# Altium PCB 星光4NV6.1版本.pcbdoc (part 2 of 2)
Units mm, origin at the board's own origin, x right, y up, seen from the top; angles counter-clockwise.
Board outline 96.4 x 47 mm, 2 copper layers (Top Layer, Bottom Layer), stack 1.58 mm thick; 27 components, 21 nets, 135 pads, 175 vias.
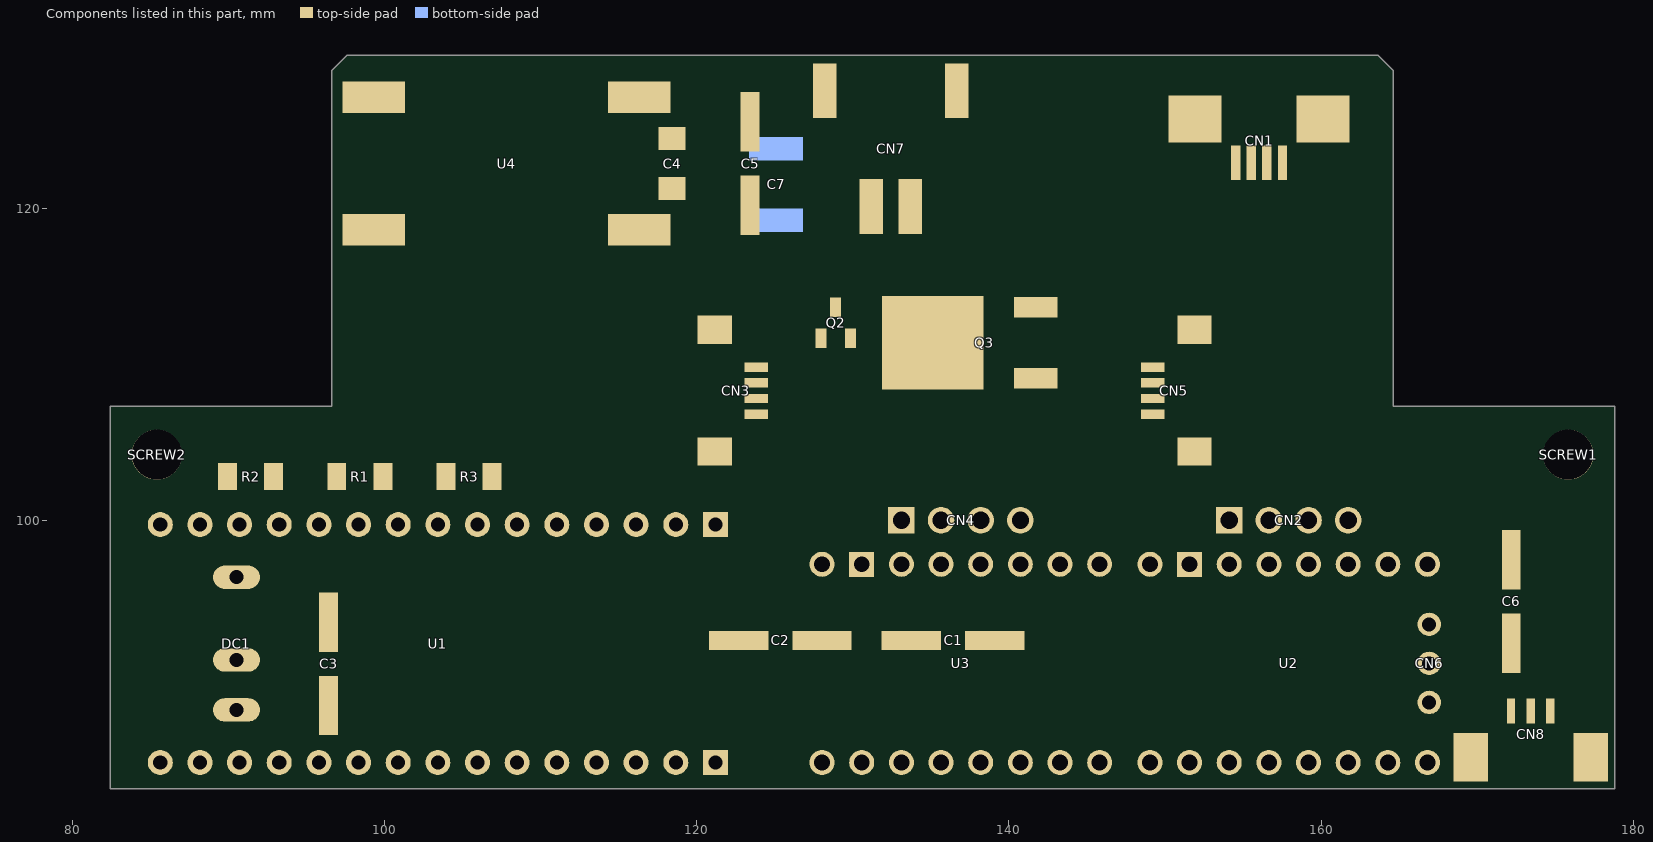
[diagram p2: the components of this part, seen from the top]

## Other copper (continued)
Bottom Layer:
  region net D8/EN: 95.603,100.813 96.003,100.813 96.005,100.76 96.012,100.712 96.023,100.669 96.037,100.63 96.055,100.595 96.077,100.563 96.128,100.505 96.189,100.45 96.256,100.394 96.328,100.33 96.403,100.253 95.203,100.253 95.278,100.33 95.35,100.394 95.417,100.45 95.478,100.505 95.529,100.563 95.551,100.595 95.569,100.63 95.583,100.669 95.594,100.712 95.601,100.76
  region net D2/X-STEP: 111.243,98.635 110.843,98.635 110.841,98.688 110.834,98.736 110.823,98.779 110.809,98.818 110.791,98.853 110.769,98.885 110.718,98.943 110.657,98.998 110.59,99.054 110.518,99.118 110.443,99.195 111.643,99.195 111.568,99.118 111.496,99.054 111.429,98.998 111.368,98.943 111.317,98.885 111.295,98.853 111.277,98.818 111.263,98.779 111.252,98.736 111.245,98.688
  region net D3/Y-STEP: 108.703,98.635 108.303,98.635 108.301,98.688 108.294,98.736 108.283,98.779 108.269,98.818 108.251,98.853 108.229,98.885 108.178,98.943 108.117,98.998 108.05,99.054 107.978,99.118 107.903,99.195 109.103,99.195 109.028,99.118 108.956,99.054 108.889,98.998 108.828,98.943 108.777,98.885 108.755,98.853 108.737,98.818 108.723,98.779 108.712,98.736 108.705,98.688
  region net 12V: 93.073,88.454 93.073,87.254 92.738,87.248 92.416,87.231 92.115,87.207 91.845,87.179 91.438,87.128 91.273,87.104 91.273,88.604 91.438,88.581 91.845,88.529 92.115,88.502 92.416,88.478 92.738,88.461
  region net 5V: 155.564,84.284 155.564,84.684 155.617,84.686 155.665,84.693 155.708,84.704 155.747,84.718 155.782,84.736 155.814,84.758 155.872,84.809 155.927,84.87 155.983,84.937 156.047,85.009 156.124,85.084 156.124,83.884 156.047,83.959 155.983,84.031 155.927,84.098 155.872,84.159 155.814,84.21 155.782,84.232 155.747,84.25 155.708,84.264 155.665,84.275 155.617,84.282
  region net 5V: 156.453,85.573 156.853,85.573 156.855,85.52 156.862,85.472 156.873,85.429 156.887,85.39 156.905,85.355 156.927,85.323 156.978,85.265 157.039,85.21 157.106,85.154 157.178,85.09 157.253,85.013 156.053,85.013 156.128,85.09 156.2,85.154 156.267,85.21 156.328,85.265 156.379,85.323 156.401,85.355 156.419,85.39 156.433,85.429 156.444,85.472 156.451,85.52
  region net 5V: 155.202,84.684 155.202,84.284 155.149,84.282 155.101,84.275 155.058,84.264 155.019,84.25 154.984,84.232 154.952,84.21 154.894,84.159 154.839,84.098 154.783,84.031 154.719,83.959 154.642,83.884 154.642,85.084 154.719,85.009 154.783,84.937 154.839,84.87 154.894,84.809 154.952,84.758 154.984,84.736 155.019,84.718 155.058,84.704 155.101,84.693 155.149,84.686
  region net 5V: 153.024,84.284 153.024,84.684 153.077,84.686 153.125,84.693 153.168,84.704 153.207,84.718 153.242,84.736 153.274,84.758 153.332,84.809 153.387,84.87 153.443,84.937 153.507,85.009 153.584,85.084 153.584,83.884 153.507,83.959 153.443,84.031 153.387,84.098 153.332,84.159 153.274,84.21 153.242,84.232 153.207,84.25 153.168,84.264 153.125,84.275 153.077,84.282
  region net 5V: 152.662,84.684 152.662,84.284 152.609,84.282 152.561,84.275 152.518,84.264 152.479,84.25 152.444,84.232 152.412,84.21 152.354,84.159 152.299,84.098 152.243,84.031 152.179,83.959 152.102,83.884 152.102,85.084 152.179,85.009 152.243,84.937 152.299,84.87 152.354,84.809 152.412,84.758 152.444,84.736 152.479,84.718 152.518,84.704 152.561,84.693 152.609,84.686
  region net 5V: 134.564,84.284 134.564,84.684 134.617,84.686 134.665,84.693 134.708,84.704 134.747,84.718 134.782,84.736 134.814,84.758 134.872,84.809 134.927,84.87 134.983,84.937 135.047,85.009 135.124,85.084 135.124,83.884 135.047,83.959 134.983,84.031 134.927,84.098 134.872,84.159 134.814,84.21 134.782,84.232 134.747,84.25 134.708,84.264 134.665,84.275 134.617,84.282
  region net 5V: 135.453,85.573 135.853,85.573 135.855,85.52 135.862,85.472 135.873,85.429 135.887,85.39 135.905,85.355 135.927,85.323 135.978,85.265 136.039,85.21 136.106,85.154 136.178,85.09 136.253,85.013 135.053,85.013 135.128,85.09 135.2,85.154 135.267,85.21 135.328,85.265 135.379,85.323 135.401,85.355 135.419,85.39 135.433,85.429 135.444,85.472 135.451,85.52
  region net 5V: 134.202,84.684 134.202,84.284 134.149,84.282 134.101,84.275 134.058,84.264 134.019,84.25 133.984,84.232 133.952,84.21 133.894,84.159 133.839,84.098 133.783,84.031 133.719,83.959 133.642,83.884 133.642,85.084 133.719,85.009 133.783,84.937 133.839,84.87 133.894,84.809 133.952,84.758 133.984,84.736 134.019,84.718 134.058,84.704 134.101,84.693 134.149,84.686
  region net 5V: 132.024,84.284 132.024,84.684 132.077,84.686 132.125,84.693 132.168,84.704 132.207,84.718 132.242,84.736 132.274,84.758 132.332,84.809 132.387,84.87 132.443,84.937 132.507,85.009 132.584,85.084 132.584,83.884 132.507,83.959 132.443,84.031 132.387,84.098 132.332,84.159 132.274,84.21 132.242,84.232 132.207,84.25 132.168,84.264 132.125,84.275 132.077,84.282
  region net 5V: 131.662,84.684 131.662,84.284 131.609,84.282 131.561,84.275 131.518,84.264 131.479,84.25 131.444,84.232 131.412,84.21 131.354,84.159 131.299,84.098 131.243,84.031 131.179,83.959 131.102,83.884 131.102,85.084 131.179,85.009 131.243,84.937 131.299,84.87 131.354,84.809 131.412,84.758 131.444,84.736 131.479,84.718 131.518,84.704 131.561,84.693 131.609,84.686
  region net 5V: 143.473,96.095 143.073,96.095 143.071,96.148 143.064,96.196 143.053,96.239 143.039,96.278 143.021,96.313 142.999,96.345 142.948,96.403 142.887,96.458 142.82,96.514 142.748,96.578 142.673,96.655 143.873,96.655 143.798,96.578 143.726,96.514 143.659,96.458 143.598,96.403 143.547,96.345 143.525,96.313 143.507,96.278 143.493,96.239 143.482,96.196 143.475,96.148
  region net $1N40669: 165.902,93.134 165.902,93.534 165.951,93.536 165.995,93.542 166.035,93.552 166.071,93.565 166.104,93.582 166.134,93.601 166.19,93.647 166.243,93.702 166.297,93.763 166.357,93.829 166.427,93.896 166.427,92.771 166.357,92.839 166.297,92.905 166.243,92.966 166.19,93.021 166.134,93.067 166.104,93.086 166.071,93.103 166.035,93.116 165.995,93.126 165.951,93.132
  region net 5V: 165.902,90.634 165.902,91.034 165.951,91.036 165.995,91.042 166.035,91.052 166.071,91.065 166.104,91.082 166.134,91.101 166.19,91.147 166.243,91.202 166.297,91.264 166.357,91.329 166.427,91.397 166.427,90.272 166.357,90.339 166.297,90.405 166.243,90.466 166.19,90.521 166.134,90.567 166.104,90.587 166.071,90.603 166.035,90.616 165.995,90.626 165.951,90.632
  region net $1N38622: 132.813,101.363 133.413,101.363 ccw(c133.926,101.363) 133.863,100.854 132.363,100.854 ccw(c132.3,101.363)
  region net $1N38620: 135.353,101.161 135.953,101.161 135.955,101.115 135.961,101.07 135.982,100.988 136.015,100.911 136.058,100.84 136.11,100.771 136.167,100.704 136.29,100.566 135.016,100.566 135.139,100.704 135.196,100.771 135.248,100.84 135.291,100.911 135.324,100.988 135.345,101.07 135.351,101.115
  region net $1N38619: 137.893,101.161 138.493,101.161 138.495,101.115 138.501,101.07 138.522,100.988 138.555,100.911 138.598,100.84 138.65,100.771 138.707,100.704 138.83,100.566 137.556,100.566 137.679,100.704 137.736,100.771 137.788,100.84 137.831,100.911 137.864,100.988 137.885,101.07 137.891,101.115
  region net $1N38618: 140.433,101.161 141.033,101.161 141.035,101.115 141.041,101.07 141.062,100.988 141.095,100.911 141.138,100.84 141.19,100.771 141.247,100.704 141.37,100.566 140.096,100.566 140.219,100.704 140.276,100.771 140.328,100.84 140.371,100.911 140.404,100.988 140.425,101.07 140.431,101.115
  region net 5V: 128.623,124.404 128.623,123.204 ccw(c128.623,111.765) 126.823,123.061 126.823,124.547 ccw(c128.623,135.843) 128.623,124.404
  region net $1N40367: 128.304,119.819 128.304,118.619 ccw(c128.304,110.85) 126.823,118.476 126.823,119.961 ccw(c128.304,127.588) 128.304,119.819
  region net D2/X-STEP: 116.147,91.262 116.43,91.545 116.471,91.498 116.506,91.457 116.524,91.441 116.545,91.428 116.571,91.419 116.601,91.414 116.278,91.09 116.273,91.121 116.264,91.146 116.251,91.167 116.234,91.186 116.194,91.221
  region net $1N38622: 147.701,109.504 147.701,110.104 148.067,110.109 148.067,109.499
  region net $1N38622: 147.634,110.104 147.634,109.504 147.268,109.499 147.268,110.109
  region net $1N38622: 146.902,109.504 146.902,110.104 147.268,110.109 147.268,109.499
  region net $1N38620: 147.634,109.104 147.634,108.504 147.268,108.499 147.268,109.109
  region net $1N38620: 146.902,108.504 146.902,109.104 147.268,109.109 147.268,108.499
  region net $1N38620: 147.701,108.504 147.701,109.104 148.067,109.109 148.067,108.499
  region net $1N38619: 146.902,107.504 146.902,108.104 147.268,108.109 147.268,107.499
  region net $1N38619: 147.634,108.104 147.634,107.504 147.268,107.499 147.268,108.109
  region net $1N38619: 147.701,107.504 147.701,108.104 148.067,108.109 148.067,107.499
  region net $1N38618: 146.902,106.504 146.902,107.104 147.268,107.109 147.268,106.499
  region net $1N38618: 147.634,107.104 147.634,106.504 147.268,106.499 147.268,107.109
  region net $1N38618: 147.701,106.504 147.701,107.104 148.067,107.109 148.067,106.499
  region net D8/EN: 96.003,102.835 95.603,102.835 95.601,102.901 95.593,102.966 95.575,103.027 95.56,103.055 95.541,103.08 96.066,103.08 96.046,103.055 96.031,103.027 96.013,102.966 96.005,102.901
  region net $1N40669: 147.52,99.026 147.12,99.026 147.124,99.088 147.128,99.141 147.127,99.166 147.121,99.19 147.11,99.214 147.091,99.239 147.549,99.239 147.53,99.214 147.519,99.19 147.513,99.166 147.512,99.141 147.516,99.088
  region net $1N40669: 147.12,99.856 147.52,99.856 147.516,99.794 147.512,99.741 147.513,99.716 147.519,99.692 147.53,99.668 147.549,99.643 147.091,99.643 147.11,99.668 147.121,99.692 147.127,99.716 147.128,99.741 147.124,99.794
  region net $1N40669: 147.52,99.78 147.12,99.78 147.124,99.842 147.128,99.895 147.127,99.92 147.121,99.944 147.11,99.968 147.091,99.993 147.549,99.993 147.53,99.968 147.519,99.944 147.513,99.92 147.512,99.895 147.516,99.842
  region net D3/Y-STEP: 109.048,91.276 109.331,91.559 109.372,91.512 109.407,91.471 109.426,91.455 109.447,91.442 109.472,91.433 109.503,91.428 109.179,91.104 109.174,91.135 109.165,91.16 109.152,91.181 109.136,91.2 109.095,91.235
  region net D3/Y-STEP: 109.918,90.971 109.636,90.689 109.595,90.735 109.56,90.776 109.541,90.792 109.52,90.805 109.495,90.815 109.464,90.819 109.788,91.143 109.792,91.112 109.802,91.087 109.815,91.066 109.831,91.047 109.872,91.012
  region net D3/Y-STEP: 109.761,90.564 110.043,90.846 110.084,90.8 110.119,90.759 110.138,90.743 110.159,90.73 110.184,90.72 110.215,90.716 109.891,90.392 109.887,90.423 109.877,90.448 109.864,90.469 109.848,90.488 109.807,90.523
  region net D2/X-STEP: 116.316,91.658 116.034,91.375 115.993,91.422 115.958,91.463 115.939,91.479 115.918,91.492 115.893,91.501 115.862,91.506 116.186,91.83 116.19,91.799 116.2,91.774 116.213,91.753 116.229,91.734 116.27,91.699
  region net D2/X-STEP: 115.446,91.963 115.729,92.245 115.77,92.199 115.805,92.158 115.823,92.142 115.845,92.129 115.87,92.119 115.9,92.115 115.577,91.791 115.572,91.822 115.563,91.847 115.55,91.868 115.534,91.887 115.493,91.922
  region net D8/EN: 95.603,102.765 96.003,102.765 95.999,102.703 95.995,102.65 95.996,102.625 96.002,102.601 96.013,102.577 96.032,102.552 95.574,102.552 95.593,102.577 95.604,102.601 95.61,102.625 95.611,102.65 95.607,102.703
  region net D8/EN: 96.003,101.935 95.603,101.935 95.607,101.997 95.611,102.05 95.61,102.075 95.604,102.099 95.593,102.124 95.574,102.148 96.032,102.148 96.013,102.124 96.002,102.099 95.996,102.075 95.995,102.05 95.999,101.997
  region net 12V: 125.222,94.199 cw(c125.222,95.655) 124.249,94.572 122.428,93.599 121.828,92.15 cw(c125.222,85.787) 125.222,92.999 125.222,94.199
  region net 12V: 123.225,98.845 cw(c113.098,98.845) 122.004,94.023 122.852,93.175 cw(c123.825,92.202) 124.798,93.175 125.646,94.023 cw(c134.552,98.845) 124.425,98.845
  region net 12V: 124.249,95.42 ccw(c127.313,98.484) 126.671,94.199 125.222,93.599 122.573,94.199 ccw(c122.573,95.303) 123.401,94.572
  region net 5V: 143.073,92.504 cw(c139.352,92.504) 142.745,90.976 143.028,90.693 cw(c143.273,90.447) 143.518,90.693 143.801,90.976 cw(c147.194,92.504) 143.473,92.504
  region net 5V: 143.414,91.362 ccw(c144.212,92.16) 144.143,91.034 143.66,90.834 142.886,91.034 ccw(c142.886,91.719) 143.132,91.08
  region net 5V: 143.414,91.08 ccw(c143.66,91.719) 143.66,91.034 142.886,90.834 142.403,91.034 ccw(c142.334,92.16) 143.132,91.362
  region net 5V: 156.853,89.175 cw(c160.636,89.175) 157.171,90.693 156.888,90.976 cw(c156.653,91.211) 156.418,90.976 156.135,90.693 cw(c152.67,89.175) 156.453,89.175
  region net 5V: 156.794,90.599 cw(c157.029,89.828) 157.029,90.634 156.277,90.834 155.794,90.634 cw(c155.741,89.546) 156.512,90.316
  region net 5V: 156.512,90.599 ccw(c156.277,89.828) 156.277,90.634 157.029,90.834 157.512,90.634 ccw(c157.565,89.546) 156.794,90.316

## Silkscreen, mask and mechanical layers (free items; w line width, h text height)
Top Silkscreen Layer:
  text "X轴" at 161.014,121.793 h2
  text "0.1U" at 122.047,121.031 h2 r90
  text "220UF" at 126.492,120.65 h1.5 r90
  text "+" at 136.144,118.11 h3.05
  text "1mm-4P / 上接抽屉" at 155.702,117.475 h1.8
  text "Y轴" at 148.568,113.792 h2
  text "Y轴" at 123.676,110.998 h2
  text "3400" at 127,109.093 h1.5
  text "30N3P" at 133.858,106.172 h1.5
  text "1mm-4P / 下接翻盖" at 111.865,101.6 h1.8
  text "2B 2A 1A 1B" at 132.08,101.346 h1.5
  text "2B 2A 1A 1B" at 153.035,101.346 h1.5
  text "1mm-4P / 下接翻盖" at 144.653,99.822 h1.8
  text "Y轴" at 126.365,99.314 h3
  text "X轴" at 165.735,99.187 h3
  text "220UF" at 170.915,93.046 h1.5 r90
  text "黄" at 157.331,92.329 h2
  text "Arduino nano" at 100.838,91.567 h2.8
  text "红" at 157.331,89.916 h2
  text "220UF" at 122.61,89.181 h1.5
  text "220UF" at 133.781,89.181 h1.5
  text "220UF" at 95.402,88.6 h1.5 r90
  text "黑" at 157.331,87.503 h2
  text "插反必烧" at 134.493,86.36 h2.2
  text "注意区分 / EN脚位" at 156.083,86.106 h2 r90
  text "舵机" at 156.337,85.979 h1.5
  text "EN" at 127.127,85.725 h3.05
  text "EN" at 148.082,85.725 h3.05
Bottom Silkscreen Layer:
  drawing of 81 lines, arcs and shapes, not listed
  text "备用激光测试" at 128.778,121.031 h1.2
  text "星光4N V6.1" at 160.909,119.126 h3.5
  text "必须调整电机驱动电位器（测电位器与GND / 之间电压），参考X轴0.32max，Y轴0.5max" at 162.941,109.601 h2.5
  text "【以上数据供参考，电机发热情况与 / 环境温度、工作加速度、最大速度、 / 负载阻力、连续工作时长等均有影响， / 若电机温度过高应休息冷却】" at 164.338,101.473 h1.8
  text "DC9-12V" at 107.315,94.996 h3
  text "注意区分EN脚方向！ / 必须调整电机驱动器的输出电流 / 防止输出过高导致电机高温、主板损坏" at 163.957,86.487 h2.5
Bottom Solder Mask Layer:
  text "流浪的星星" at 163.576,125.222 h4
Mechanical Layer:
  lines w0.003: 135.597,114.983 138.597,114.983 138.597,117.983 135.597,117.983 135.597,114.983 ; 142.623,114.983 145.623,114.983 145.623,117.983 142.623,117.983 142.623,114.983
